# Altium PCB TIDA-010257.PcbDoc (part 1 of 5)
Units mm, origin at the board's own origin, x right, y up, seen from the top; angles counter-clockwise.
Board outline 250 x 270 mm, 2 copper layers (Top Layer, Bottom Layer), stack 1.575 mm thick; 458 components, 220 nets, 1154 pads, 1226 vias.
Unrouted connection lines stored in the file: 314.
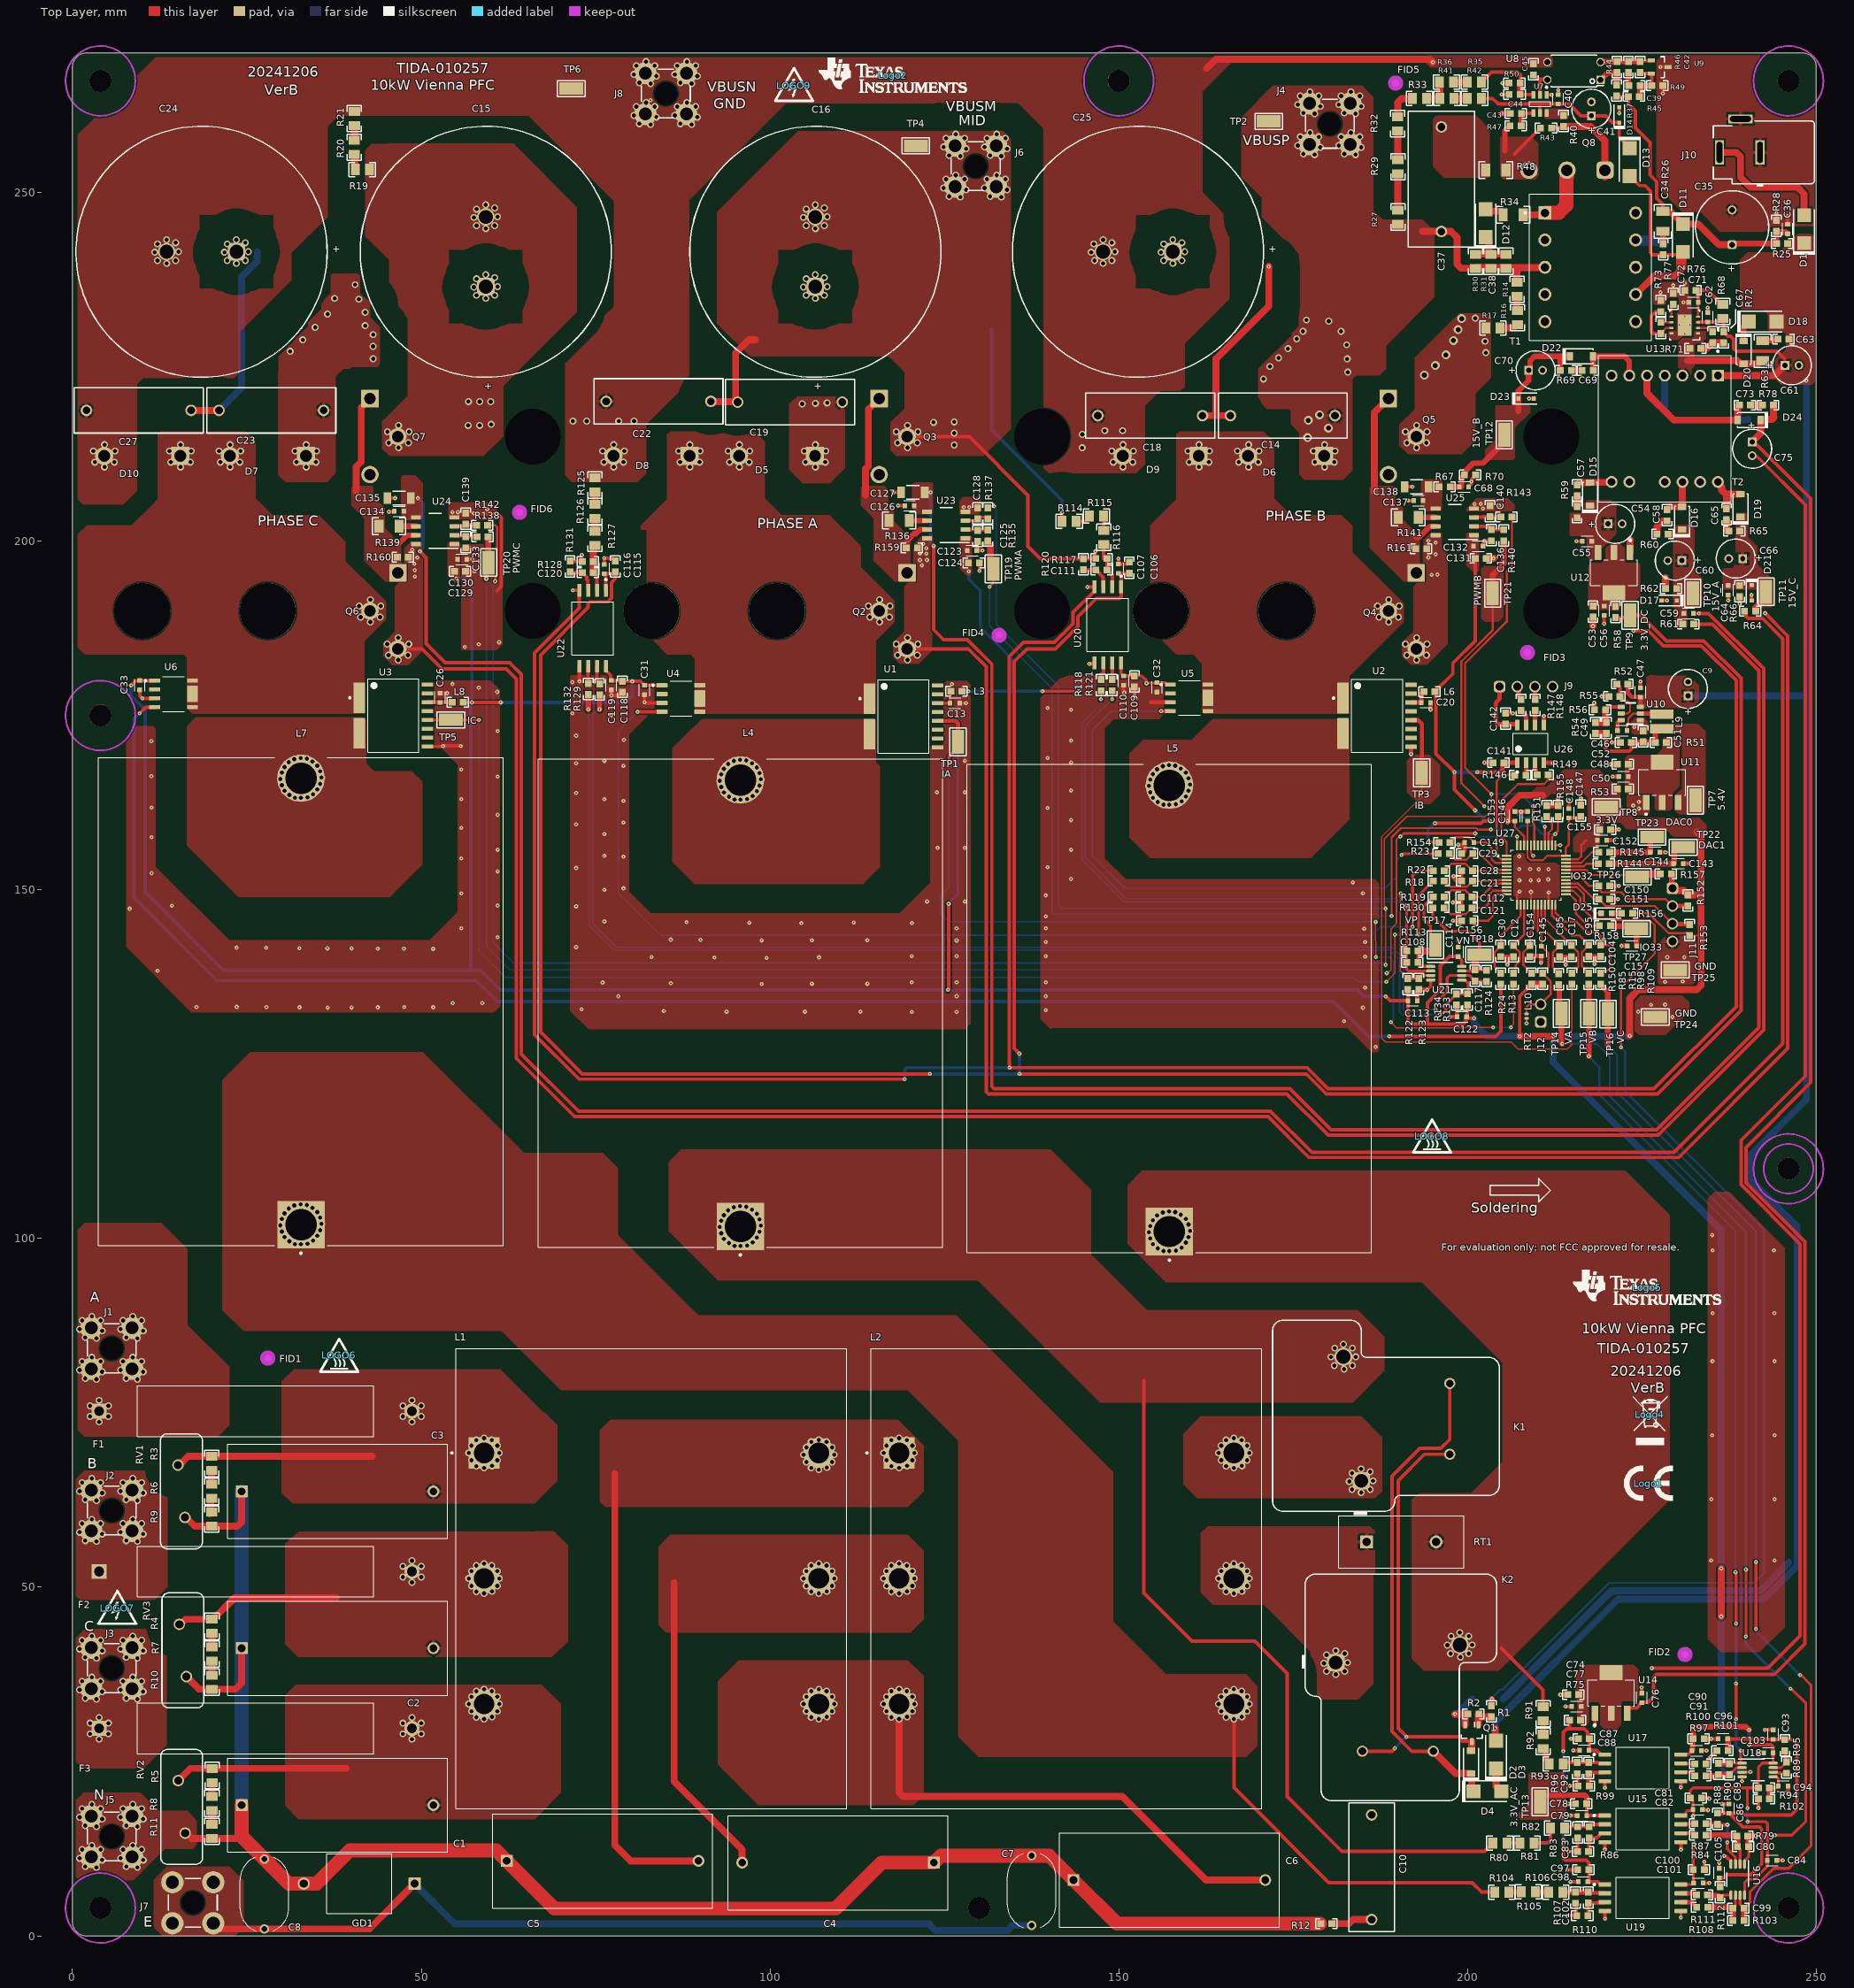
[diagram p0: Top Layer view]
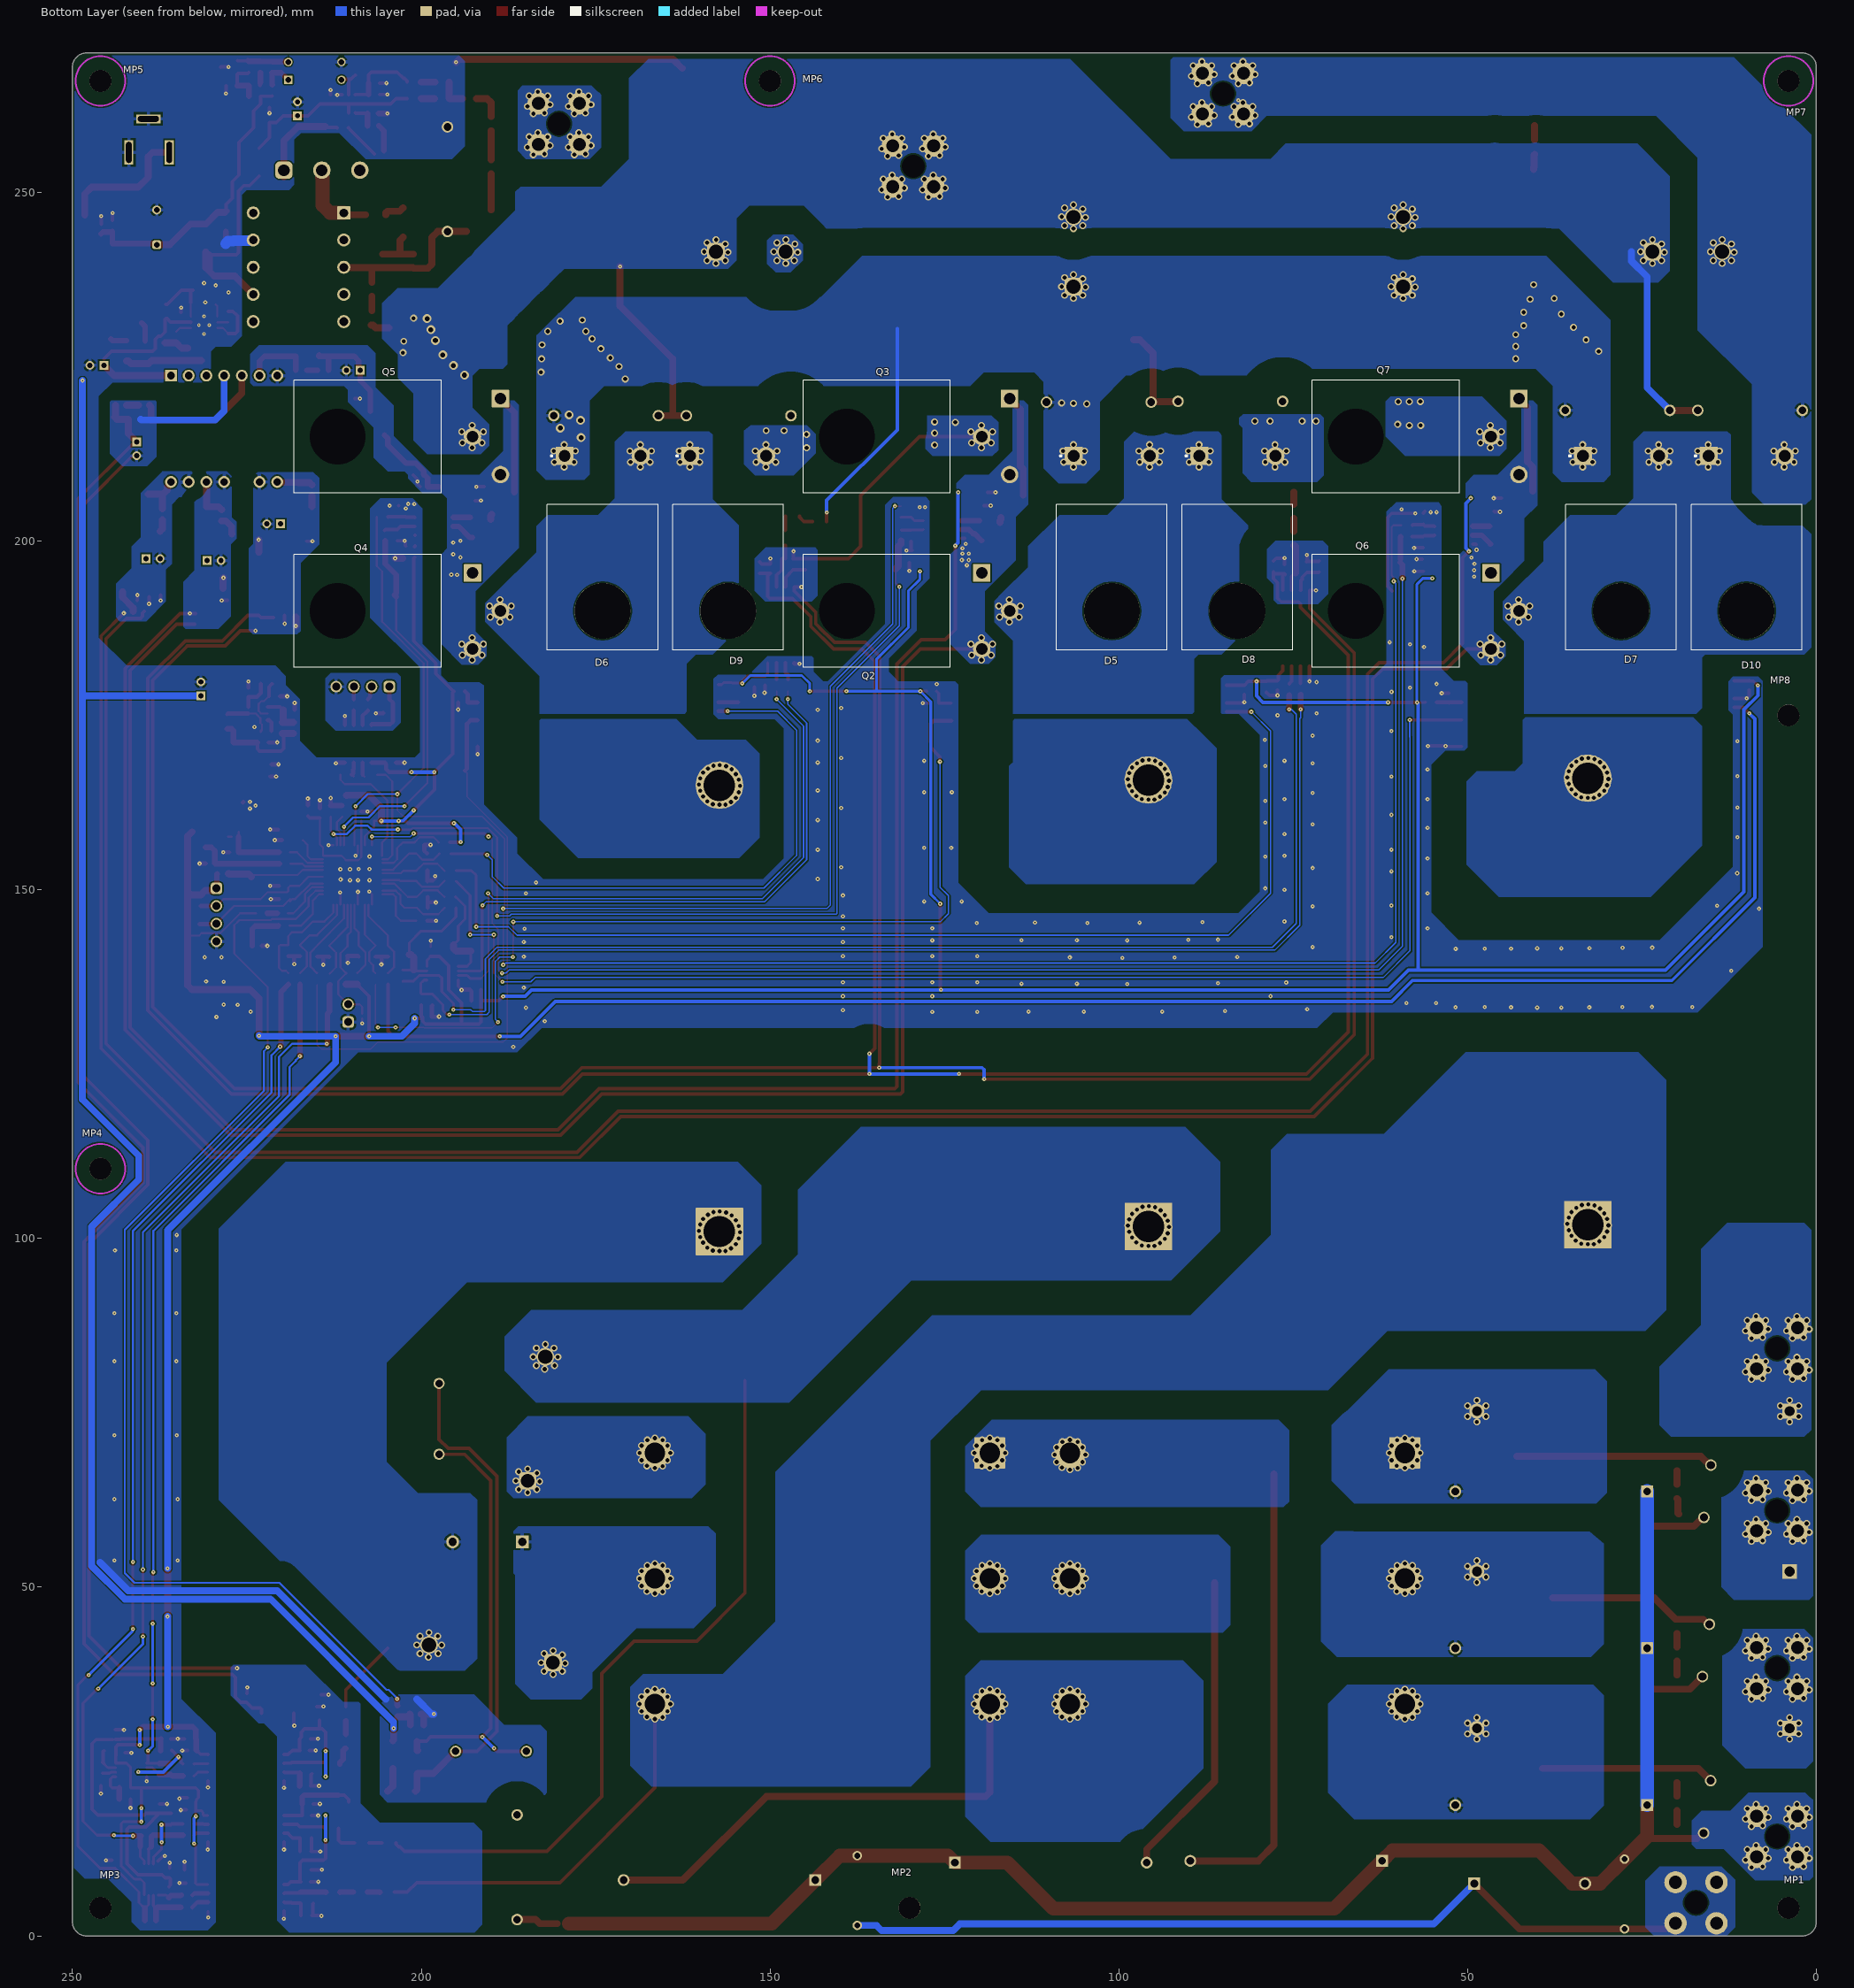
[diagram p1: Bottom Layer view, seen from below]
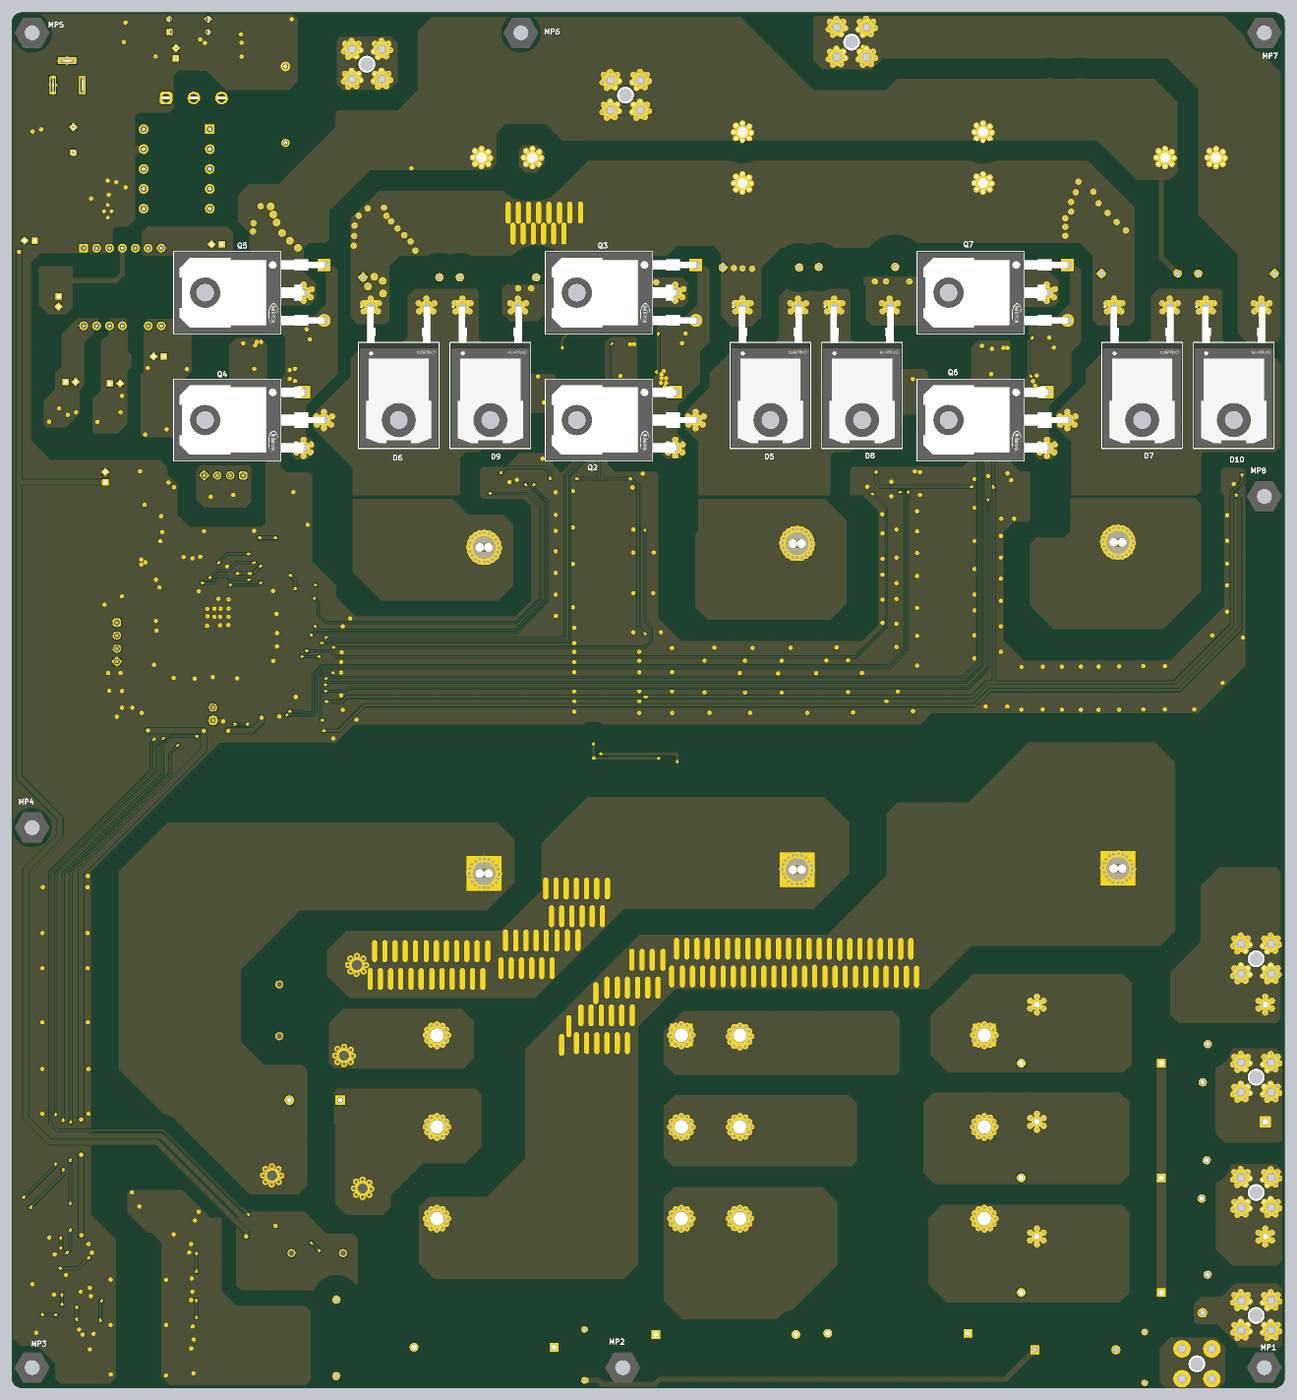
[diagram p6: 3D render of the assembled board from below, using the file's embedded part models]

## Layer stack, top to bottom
Top Solder: solder mask 0.0102, Solder Resist, Dk 3.5
Top Layer: signal copper 0.0356
Dielectric1: core 1.5037, FR-4 High Tg, Dk 4.8
Bottom Layer: signal copper 0.0356
Bottom Solder: solder mask 0.0102, Solder Resist, Dk 3.5

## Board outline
2,0 cw(c2,2) 0,2 0,268 cw(c2,268) 2,270 248,270 cw(c248,268) 250,268 250,2 cw(c248,2) 248,0

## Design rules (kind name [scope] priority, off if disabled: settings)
Clearance A2B [InNetClass('ACA') vs InNetClass('ACB')] p1: gap=4 ignorepadtopadclearanceinfootprint=FALSE
Clearance Ignore [All vs WithinRoom('Ignore1')    or WithinRoom('IsolatedPower')] p2: gap=0.2 ignorepadtopadclearanceinfootprint=FALSE
Clearance GA2B [InNetClass('GateA') vs InNetClass('ACB')] p3: gap=2 ignorepadtopadclearanceinfootprint=FALSE
Clearance GA2C [InNetClass('GateA') vs InNetClass('GateC')] p4: gap=2 ignorepadtopadclearanceinfootprint=FALSE
Clearance GB2C [InNetClass('GateB') vs InNetClass('GateC')] p5: gap=2 ignorepadtopadclearanceinfootprint=FALSE
Clearance A2C [InNetClass('ACA') vs InNetClass('ACC')] p6: gap=4 ignorepadtopadclearanceinfootprint=FALSE
Clearance B2C [InNetClass('ACB') vs InNetClass('ACC')] p7: gap=4 ignorepadtopadclearanceinfootprint=FALSE
Clearance DCBUSP2N [InNetClass('DCBUSP') vs InNetClass('PGND')] p8: gap=5.5 ignorepadtopadclearanceinfootprint=FALSE
Clearance DCBUSP2M [InNetClass('DCBUSP') vs InNetClass('DCBUSM')] p9: gap=4 ignorepadtopadclearanceinfootprint=FALSE
Clearance DCBUSM2N [InNetClass('DCBUSM') vs InNetClass('PGND')] p10: gap=2 ignorepadtopadclearanceinfootprint=FALSE
Clearance A2GND [InNetClass('ACA') vs InNetClass('PGND')] p11: gap=3 ignorepadtopadclearanceinfootprint=FALSE
Clearance B2GND [InNetClass('ACB') vs InNetClass('PGND')] p12: gap=3 ignorepadtopadclearanceinfootprint=FALSE
Clearance C2GND [InNetClass('ACC') vs InNetClass('PGND')] p13: gap=3 ignorepadtopadclearanceinfootprint=FALSE
Clearance GA2GND [InNetClass('GateA') vs InNetClass('PGND')] p14: gap=2 ignorepadtopadclearanceinfootprint=TRUE
Clearance GB2GND [InNetClass('ACB') vs InNetClass('PGND')] p15: gap=2 ignorepadtopadclearanceinfootprint=FALSE
Clearance GC2GND [InNetClass('ACC') vs InNetClass('PGND')] p16: gap=2 ignorepadtopadclearanceinfootprint=FALSE
Clearance [All] p17: gap=0.2 ignorepadtopadclearanceinfootprint=FALSE
Height [All] p1: minheight=0 maxheight=50 prefheight=12.7
HoleSize [All] p1: absolutevalues=TRUE maxlimit=10 minlimit=0.025 maxpercent=80.000 minpercent=20.000
HoleToHoleClearance [All] p1: gap=0.1 allowstackedmicrovias=TRUE
MinimumSolderMaskSliver [All] p1: minsoldermaskwidth=0.001
PolygonConnect PolygonReleif [All vs InComponent('J10') or InComponent('J35')   or  InComponent('C75') or InComponent('C54')   or InComponent('C66') or InComponent('C60') or InComponent('C35') or InComponent('C1')  or InComponent('C2') or InComponent('C3') or InComponent('C9') or InComponent('C61') or InComponent('C27') or InComponent('C23')  or InComponent('C19') or InComponent('C22')   or InComponent('C18') or InComponent('C14') or InComponent('C41') or InComponent('U8') or InComponent('C70')   or InComponent('RT1')  or InComponent('J9')  or InComponent('J11')   or InComponent('J12') or InComponent('T2')] p1: connectstyle=Relief reliefconductorwidth=0.5 reliefentries=4 polygonreliefangle="90 Angle" airgapwidth=0.3
PolygonConnect PolygonDirect [All] p2: connectstyle=Direct reliefconductorwidth=0.22 reliefentries=4 polygonreliefangle="90 Angle" airgapwidth=0.3
RoomDefinition IsolatedPower [InComponentClass('IsolatedPower')] p1: confinementstyle=ConfineIn formatcopy=TRUE lockcomponents=FALSE outline 194.153,238.75 250,238.75 250,184.359 194.153,184.359
RoomDefinition Ignore1 [InComponentClass('Components Class1')] p2: confinementstyle=ConfineIn formatcopy=TRUE lockcomponents=FALSE outline 161.5,268.27 162.879,270 221.417,270 223.25,267.699 223.25,240.373 220.006,236.301 170.181,236.301 161.5,247.198
RoutingVias [All] p1: holewidth=0.2 width=0.6 viastyle="Through Hole" minholewidth=0.2 minwidth=0.6 maxholewidth=2.6 maxwidth=3
SilkToBoardRegionClearance [Not ((IsComment or IsDesignator) And (Hide <> 'False')) and not InRegion(1000,500,4000,800)] p1:
SilkToSilkClearance [All] p1: silktosilkclearance=0
SilkToSolderMaskClearance [IsPad] p1: minsilkscreentomaskgap=0 clearancetoexposedcopper=TRUE
SolderMaskExpansion [All] p1: expansion=0.102 istentingtop=FALSE
Width [All] p1: maxlimit=5 minlimit=0.2 preferedwidth=0.2 minimp=50.000000 maximp=50.000000 favimp=50.000000
23 further rules are at their usual default settings.

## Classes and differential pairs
net class PGND: 1.65V 3.3V 5.4V 5V_ISO 15V #GD_ENABLE A3.3V BROWNOUT DAC0 DAC1 GND_ISO HS_TEMP_AD IA_AD IB_AD IC_AD LED1C_C2K MCU_TCK MCU_TMS NetC34_1 NetC35_1 NetC39_1 NetC39_2 NetC40_2 NetC42_2 NetC43_1 NetC45_2 NetC46_1 NetC46_2 NetC48_1 NetC49_1 NetC63_2 NetC67_1 NetC71_2 NetC72_1 NetC80_1 NetC80_2 NetC89_1 NetC89_2 NetC94_2 NetC99_1 NetC99_2 NetC108_1 NetC108_2 NetC117_1 NetC117_2 NetC125_1 NetC128_1 NetC133_1 NetC136_1 NetC139_1 NetC140_1 NetC143_2 NetC144_2 NetC146_1 NetC156_1 NetC157_2 NetD3_1 NetD18_1 NetD20_2 NetD25_1 NetQ1_1 NetQ8_1 NetQ8_3 NetR22_2 NetR23_2 NetR24_2 NetR33_1 NetR35_2 NetR37_1 NetR40_1 NetR41_2 NetR52_1 NetR72_1 NetR73_1 NetR73_2 NetR84_1 NetR87_1 NetR87_2 NetR89_1 NetR89_2 NetR97_1 NetR100_1 NetR100_2 NetR108_1 NetR111_1 NetR111_2 NetR118_1 NetR121_1 NetR121_2 NetR129_1 NetR132_1 NetR132_2 NetR146_2 NetR147_1 NetR148_1 NetR149_2 NetR151_1 NetR157_1 NetR158_1 NetU4_2 NetU5_2 NetU6_2 NetU24_4 NetU24_7 NetU24_10 NetU24_16 NetU24_27 NetU24_29 NetU24_31 NetU24_39 NetU24_41 NetU24_47 PWMA PWMB PWMC RELAY RELAY_DRIVE RX SYS_RX SYS_TX TMPA TMPB TMPC TX V_BUSN_AD V_BUSP_AD V_Relay VA_AD Vaux VB_AD VBUSN VC_AD XRSn
net class GateC: 15V_GateC GND_GATEC NetC64_2 NetC65_1 NetC65_2 NetR139_1 QC_C QC_GATE
net class GateB: 15V_GateB GND_GATEB NetC68_2 NetC69_1 NetC69_2 NetR141_1 QB_C QB_GATE
net class GateA: 15V_GateA GND_GATEA NetC58_1 NetC58_2 NetC59_2 NetR136_1 QA_C QA_GATE
net class EARTH: EGND NetC1_2 V_L3
net class DCBUSP: NetC38_2 NetD12_2 NetQ8_2 NetR27_1 NetR29_1 NetR32_1 NetR33_1 NetT1_2 VBUSP
net class DCBUSM: 3.3V_DCSensing NetC53_1 NetC54_1 NetC57_1 NetC57_2 NetC111_1 NetC111_2 NetC120_1 NetC120_2 NetR115_2 NetR126_2 NetU11_4 VBUSM VBUSP
net class ACB: NetC2_2 NetC4_2 NetK2_1 QB_C V_B V_B2 V_L2 VBUSM VN
net class ACN: 3.3V_ACSensing GND_ACSensing NetC10_1 NetC73_1 NetC73_2 NetC74_1 NetC75_1 NetC83_1 NetC83_2 NetC92_1 NetC92_2 NetC102_1 NetC102_2 NetR81_2 NetR92_2 NetR105_2 NetU9_4 VN
net class ACC: EGND NetC1_2 NetC6_2 NetL7_2 QC_C V_C V_L3 VN
net class ACA: NetC3_2 NetC5_2 NetK1_1 NetL4_2 QA_C V_A V_L1 VN
component class PowerStage: C12 C13 C14 C15 C16 C17 C18 C19 C20 C21 C22 C23 C24 C25 C26 C27 C28 C29 C30 C31 C32 C33 D5 D6 D7 D8 D9 D10 L3 L4 L5 L6 L7 L8 Q2 Q3 Q4 Q5 Q6 Q7 R13 R14 R15 R16 R17 R18 R19 R20 R21 R22 R23 R24 TP1 TP2 TP3 TP4 TP5 TP6 U1 U2 U3 U4 U5 U6
component class OutputVoltageSensing: C106 C107 C108 C109 C110 C111 C112 C113 C114 C115 C116 C117 C118 C119 C120 C121 C122 R113 R114 R115 R116 R117 R118 R119 R120 R121 R122 R123 R124 R125 R126 R127 R128 R129 R130 R131 R132 R133 R134 TP17 TP18 U20 U21 U22
component class Main: D1 J1 J2 J3 J4 J5 J6 J7 J8 J9 J10
component class IsolatedPower: C53 C54 C55 C56 C57 C58 C59 C60 C61 C62 C63 C64 C65 C66 C67 C68 C69 C70 C71 C72 C73 C74 C75 C76 C77 D15 D16 D17 D18 D19 D20 D21 D22 D23 D24 R58 R59 R60 R61 R62 R63 R64 R65 R66 R67 R68 R69 R70 R71 R72 R73 R75 R76 R77 R78 T2 TP9 TP10 TP11 TP12 TP13 U12 U13 U14
component class InputVoltageSensing: C78 C79 C80 C81 C82 C83 C84 C85 C86 C87 C88 C89 C90 C91 C92 C93 C94 C95 C96 C97 C98 C99 C100 C101 C102 C103 C104 C105 R79 R80 R81 R82 R83 R84 R85 R86 R87 R88 R89 R90 R91 R92 R93 R94 R95 R96 R97 R98 R99 R100 R101 R102 R103 R104 R105 R106 R107 R108 R109 R110 R111 R112 TP14 TP15 TP16 U15 U16 U17 U18 U19
component class Header: J9 J11 J12
component class GateDrivers: C123 C124 C125 C126 C127 C128 C129 C130 C131 C132 C133 C134 C135 C136 C137 C138 C139 C140 R135 R136 R137 R138 R139 R140 R141 R142 R143 R159 R160 R161 TP19 TP20 TP21 U23 U24 U25
component class EMCInputFilter: C1 C2 C3 C4 C5 C6 C7 C8 C10 D2 D3 D4 F1 F2 F3 GD1 K1 K2 L1 L2 Q1 R1 R2 R3 R4 R5 R6 R7 R8 R9 R10 R11 R12 RT1 RV1 RV2 RV3
component class Controller: C141 C142 C143 C144 C145 C146 C147 C148 C149 C150 C151 C152 C153 C154 C155 C156 C157 D25 J11 J12 L10 R144 R145 R146 R147 R148 R149 R150 R151 R152 R153 R154 R155 R156 R157 R158 RT2 TP22 TP23 TP24 TP25 TP26 TP27 U26 U27
component class AuxPower: C9 C34 C35 C36 C37 C38 C39 C40 C41 C42 C43 C44 C45 C46 C47 C48 C49 C50 C51 C52 D11 D12 D13 D14 L9 Q8 R25 R26 R27 R28 R29 R30 R31 R32 R33 R34 R35 R36 R37 R40 R41 R42 R43 R44 R45 R46 R47 R48 R49 R50 R51 R52 R53 R54 R55 R56 T1 TP7 TP8 U7 U8 U9 U10 U11
component class Logo: Logo2 Logo5
component class Hardware: FID1 FID2 FID3 FID4 FID5 FID6 Logo1 Logo2 Logo3 Logo4 Logo5 LOGO6 LOGO7 LOGO8 LOGO9 MP1 MP2 MP3 MP4 MP5 MP6 MP7 MP8
component class FiducialMark: FID1 FID2 FID3 FID4 FID5 FID6

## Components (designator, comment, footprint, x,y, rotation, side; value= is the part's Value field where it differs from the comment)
C1 "890334027012CS" FP-890334027012CS_RADIAL-MFG 38,18.75 r0 top value=1.2µF
C2 "890334027012CS" FP-890334027012CS_RADIAL-MFG 38,41.25 r0 top value=1.2µF
C3 "890334027012CS" FP-890334027012CS_RADIAL-MFG 38,63.75 r0 top value=1.2µF
C4 "890334027012CS" FP-890334027012CS_RADIAL-MFG 109.75,10.5 r180 top value=1.2µF
C5 "890334027012CS" FP-890334027012CS_RADIAL-MFG 76,10.75 r0 top value=1.2µF
C6 "890334027012CS" FP-890334027012CS_RADIAL-MFG 157.25,8 r0 top value=1.2µF
C7 "DE1E3KX222MA4BL01" CAPRD1000W60D900H1200 137.5,6.5 r270 top value=2200pF
C8 "DE1E3KX222MA4BL01" CAPRD1000W60D900H1200 27.5,6 r270 top value=2200pF
C9 "EKZN350ELL470ME11D" Chemi-Con_500x1100 231.591,178.82 r90 top value=47uF
C10 "890334025017" WCAP-FTXX_P15PL20_1800x600 186.25,9.846 r90 top value=0.1uF
C12 "GRM188R71H102KA01D" 0603 206.563,141.215 r270 top value=1000pF
C13 "GCM188R71H104KA57J" FP-GCM188R71H104KA57J_0603-MFG 126.5,176.78 r0 top value=100nF
C14 "890334025017" WCAP-FTXX_P15PL20_1800x600 173.5,218 r180 top value=0.1uF
C15 "MAL215757471E3" 157PUM-SI_3500x5000 59.25,241.5 r90 top locked value=470uF
C16 "MAL215757471E3" 157PUM-SI_3500x5000 106.5,241.5 r90 top locked value=470uF
C17 "GRM188R71H102KA01D" 0603 214.904,141.228 r270 top value=1000pF
C18 "890334025017" WCAP-FTXX_P15PL20_1800x600 154.5,218 r180 top value=0.1uF
C19 "890334025017" WCAP-FTXX_P15PL20_1800x600 102.86,219.935 r180 top value=0.1uF
C20 "GCM188R71H104KA57J" FP-GCM188R71H104KA57J_0603-MFG 194.028,176.862 r0 top value=100nF
C21 "GRM188R71H102KA01D" 0603 199.914,151.252 r180 top value=1000pF
C22 "890334025017" WCAP-FTXX_P15PL20_1800x600 84.009,220.053 r180 top value=0.1uF
C23 "890334025017" WCAP-FTXX_P15PL20_1800x600 28.5,218.75 r180 top value=0.1uF
C24 "MAL215757471E3" 157PUM-SI_3500x5000 18.5,241.5 r180 top locked value=470uF
C25 "MAL215757471E3" 157PUM-SI_3500x5000 152.75,241.5 r180 top locked value=470uF
C26 "GCM188R71H104KA57J" FP-GCM188R71H104KA57J_0603-MFG 52.683,177.54 r90 top value=100nF
C27 "890334025017" WCAP-FTXX_P15PL20_1800x600 9.5,218.75 r180 top value=0.1uF
C28 "GRM188R71H102KA01D" 0603 199.914,152.752 r180 top value=1000pF
C29 "GRM188R71H102KA01D" 0603 199.949,155.22 r180 top value=1000pF
C30 "GRM188R71H102KA01D" 0603 204.772,141.218 r270 top value=1000pF
C31 "GCM188R71H104KA57J" FP-GCM188R71H104KA57J_0603-MFG 82,178.659 r90 top value=100nF
C32 "GCM188R71H104KA57J" FP-GCM188R71H104KA57J_0603-MFG 155.486,179.03 r90 top value=100nF
C33 "GCM188R71H104KA57J" FP-GCM188R71H104KA57J_0603-MFG 9.646,179.343 r90 top value=100nF
C34 "GRM1885C2A101JA01D" 0603 228.058,241.868 r270 top value=100pF
C35 "35ZLG470MEFC10X20" ZLG_1000x2000 237.924,245 r90 top value=470uF
C36 "GCM188R71H104KA57J" FP-GCM188R71H104KA57J_0603-MFG 245.885,244.75 r270 top value=100nF
C37 "890493425009CS" WCAP-FTBE_L18W8.5H15 196.25,251.907 r270 top
C38 "GRM21AR72E102KW01D" 0805_HV 205.521,240.141 r90 top value=1000pF
C39 "GRM188R71H102KA01D" 0603 223.935,265.328 r0 top value=1000pF
C40 "GCM188R71H104KA57J" FP-GCM188R71H104KA57J_0603-MFG 213,263.375 r270 top value=100nF
C41 "UPW1V100MDD6" PW_500x700 217.75,262 r90 top value=10uF
C42 "GRM1885C2A101JA01D" 0603 224.75,268.007 r90 top value=100pF
C43 "885012206081" 0603 206.921,261.344 r180 top value=470pF
C44 "GRM1885C2A101JA01D" 0603 206.746,264.062 r180 top value=100pF
C45 "GRM188R71H102KA01D" 0603 209.46,267.653 r270 top value=1000pF
C46 "GCM188R71H104KA57J" FP-GCM188R71H104KA57J_0603-MFG 222.168,172.822 r180 top value=100nF
C47 "GCM188R71H104KA57J" FP-GCM188R71H104KA57J_0603-MFG 224.776,178.309 r270 top value=100nF
C48 "GRM188Z71A106MA73D" 0603 222.253,168 r180 top value=10uF
C49 "GRM1885C2A101JA01D" 0603 219.903,173.226 r270 top value=100pF
C50 "GCM188R71H104KA57J" FP-GCM188R71H104KA57J_0603-MFG 222.355,166.25 r0 top value=100nF
C51 "GRM188Z71A106MA73D" 0603 225.151,172.016 r90 top value=10uF
C52 "GRM188Z71A106MA73D" 0603 222.701,171.129 r180 top value=10uF
C53 "GRM188Z71A106MA73D" 0603 217.975,189.91 r270 top value=10uF
C54 "EKZN350ELL470ME11D" Chemi-Con_500x1100 221.156,202.487 r0 top value=47uF
C55 "GCM188R71H104KA57J" FP-GCM188R71H104KA57J_0603-MFG 217.143,199.993 r0 top value=100nF
C56 "GCM188R71H104KA57J" FP-GCM188R71H104KA57J_0603-MFG 219.578,190.035 r90 top value=100nF
C57 "GRM1885C2A101JA01D" 0603 215.691,207.275 r90 top value=100pF
C58 "GRM1885C2A101JA01D" 0603 228.611,203.707 r90 top value=100pF
C59 "GCM188R71H104KA57J" FP-GCM188R71H104KA57J_0603-MFG 231.691,189.637 r180 top value=100nF
C60 "EKZN350ELL470ME11D" Chemi-Con_500x1100 229.711,197.211 r180 top value=47uF
C61 "EKZN350ELL470ME11D" Chemi-Con_500x1100 246.5,225.22 r0 top value=47uF
C62 "GCM188R71H104KA57J" FP-GCM188R71H104KA57J_0603-MFG 234.453,232.117 r270 top value=100nF
C63 "GRM1885C2A101JA01D" 0603 245.294,228.983 r180 top value=100pF
C64 "GCM188R71H104KA57J" FP-GCM188R71H104KA57J_0603-MFG 237.371,192.975 r90 top value=100nF
C65 "GRM1885C2A101JA01D" 0603 237.127,203.865 r90 top value=100pF
C66 "EKZN350ELL470ME11D" Chemi-Con_500x1100 238.448,197.5 r180 top value=47uF
C67 "GRM1885C2A101JA01D" 0603 236.71,229.221 r90 top value=100pF
C68 "GCM188R71H104KA57J" FP-GCM188R71H104KA57J_0603-MFG 199.489,207.807 r180 top value=100nF
C69 "GRM1885C2A101JA01D" 0603 217.215,224.5 r0 top value=100pF
C70 "EKZN350ELL470ME11D" Chemi-Con_500x1100 209.75,224.5 r0 top value=47uF
C71 "GCM188R71H104KA57J" FP-GCM188R71H104KA57J_0603-MFG 232.376,234.238 r0 top value=100nF
C72 "GCM188R72A103KA37J" 0603 229.477,234.749 r90 top value=0.01uF
C73 "GRM1885C2A101JA01D" 0603 239.757,219.5 r180 top value=100pF
C74 "GRM188Z71A106MA73D" 0603 215.148,34.584 r180 top value=10uF
C75 "EKZN350ELL470ME11D" Chemi-Con_500x1100 240.8,213.25 r270 top value=47uF
C76 "GCM188R71H104KA57J" FP-GCM188R71H104KA57J_0603-MFG 225,34.123 r270 top value=100nF
C77 "GCM188R71H104KA57J" FP-GCM188R71H104KA57J_0603-MFG 215.622,32.892 r0 top value=100nF
C78 "GRJ188R71E105KE11D" 0603 216.275,18.923 r180 top value=1uF
C79 "GCM188R71H104KA57J" FP-GCM188R71H104KA57J_0603-MFG 216.4,17.251 r0 top value=100nF
C80 "GRM188R71H102KA01D" 0603 239.487,12.787 r180 top value=1000pF
C81 "GRJ188R71E105KE11D" 0603 232.745,19.787 r180 top value=1uF
C82 "GCM188R71H104KA57J" FP-GCM188R71H104KA57J_0603-MFG 233,18.096 r0 top value=100nF
C83 "GRM1885C2A101JA01D" 0603 217.426,14.846 r270 top value=100pF
C84 "GCM188R71H104KA57J" FP-GCM188R71H104KA57J_0603-MFG 243.649,10.832 r180 top value=100nF
C85 "GRM188R71H102KA01D" 0603 213.198,141.192 r90 top value=1000pF
C86 "GCM188R71H104KA57J" FP-GCM188R71H104KA57J_0603-MFG 237.509,18.248 r270 top value=100nF
C87 "GRJ188R71E105KE11D" 0603 216.672,28.265 r180 top value=1uF
C88 "GCM188R71H104KA57J" FP-GCM188R71H104KA57J_0603-MFG 216.736,26.603 r0 top value=100nF
C89 "GRM188R71H102KA01D" 0603 237.543,23.896 r270 top value=1000pF
C90 "GRJ188R71E105KE11D" 0603 233.125,28.265 r180 top value=1uF
C91 "GCM188R71H104KA57J" FP-GCM188R71H104KA57J_0603-MFG 232.843,26.566 r0 top value=100nF
C92 "GRM1885C2A101JA01D" 0603 217.349,24.062 r270 top value=100pF
C93 "GCM188R71H104KA57J" FP-GCM188R71H104KA57J_0603-MFG 243.816,28.868 r270 top value=100nF
C94 "GCM188R71H104KA57J" FP-GCM188R71H104KA57J_0603-MFG 245.25,21.5 r180 top value=100nF
C95 "GRM188R71H102KA01D" 0603 217.391,141.278 r90 top value=1000pF
C96 "GCM188R71H104KA57J" FP-GCM188R71H104KA57J_0603-MFG 236.617,28.265 r0 top value=100nF
C97 "GRJ188R71E105KE11D" 0603 216.587,9.469 r180 top value=1uF
C98 "GCM188R71H104KA57J" FP-GCM188R71H104KA57J_0603-MFG 216.565,7.754 r0 top value=100nF
C99 "GRM188R71H102KA01D" 0603 238.835,3.958 r180 top value=1000pF
C100 "GRJ188R71E105KE11D" 0603 233.141,9.469 r180 top value=1uF
C101 "GCM188R71H104KA57J" FP-GCM188R71H104KA57J_0603-MFG 233.076,7.567 r0 top value=100nF
C102 "GRM1885C2A101JA01D" 0603 217.315,5.498 r270 top value=100pF
C103 "GCM188R71H104KA57J" FP-GCM188R71H104KA57J_0603-MFG 243.121,26.25 r0 top value=100nF
C104 "GRM188R71H102KA01D" 0603 219.069,141.278 r90 top value=1000pF
C105 "GCM188R71H104KA57J" FP-GCM188R71H104KA57J_0603-MFG 236.076,9.009 r270 top value=100nF
C106 "GRJ188R71E105KE11D" 0603 151.5,196.214 r90 top value=1uF
C107 "GCM188R71H104KA57J" FP-GCM188R71H104KA57J_0603-MFG 149.953,196.043 r270 top value=100nF
C108 "GRM188R71H102KA01D" 0603 192.078,139.586 r180 top value=1000pF
C109 "GRJ188R71E105KE11D" 0603 152.25,179.88 r90 top value=1uF
C110 "GCM188R71H104KA57J" FP-GCM188R71H104KA57J_0603-MFG 150.69,179.995 r270 top value=100nF
C111 "GRM1885C2A101JA01D" 0603 147.5,195.868 r180 top value=100pF
C112 "GRM188R71H102KA01D" 0603 199.877,148.995 r0 top value=1000pF
C113 "GCM188R71H104KA57J" FP-GCM188R71H104KA57J_0603-MFG 192.125,134.101 r180 top value=100nF
C114 "GCM188R71H104KA57J" FP-GCM188R71H104KA57J_0603-MFG 198.648,141.106 r90 top value=100nF
C115 "GRJ188R71E105KE11D" 0603 77.815,196.366 r90 top value=1uF
C116 "GCM188R71H104KA57J" FP-GCM188R71H104KA57J_0603-MFG 76.25,196 r270 top value=100nF
C117 "GRM188R71H102KA01D" 0603 201.092,137.719 r270 top value=1000pF
C118 "GRJ188R71E105KE11D" 0603 78.815,179.105 r90 top value=1uF
C119 "GCM188R71H104KA57J" FP-GCM188R71H104KA57J_0603-MFG 77.25,179.346 r270 top value=100nF
C120 "GRM1885C2A101JA01D" 0603 73.874,195.475 r180 top value=100pF
C121 "GRM188R71H102KA01D" 0603 199.877,147.428 r0 top value=1000pF
C122 "GCM188R71H104KA57J" FP-GCM188R71H104KA57J_0603-MFG 199.18,131.8 r0 top value=100nF
C123 "GRJ188R71E105KE11D" 0603 129.227,196.905 r0 top value=1uF
C124 "GCM188R71H104KA57J" FP-GCM188R71H104KA57J_0603-MFG 128.963,198.668 r180 top value=100nF
C125 "GRM188R71H102KA01D" 0603 129.75,200.75 r270 top value=1000pF
C126 "GCM188R71H104KA57J" FP-GCM188R71H104KA57J_0603-MFG 120.004,205.093 r0 top value=100nF
C127 "GRM31CR61H106KA12L" 1206_180 120.484,207 r180 top value=10uF
C128 "GRM188R71H102KA01D" 0603 129.75,203.971 r90 top value=1000pF
C129 "GRJ188R71E105KE11D" 0603 55.55,195.675 r0 top value=1uF
C130 "GCM188R71H104KA57J" FP-GCM188R71H104KA57J_0603-MFG 55.85,197.402 r180 top value=100nF
C131 "GRJ188R71E105KE11D" 0603 201.876,197.542 r0 top value=1uF
C132 "GCM188R71H104KA57J" FP-GCM188R71H104KA57J_0603-MFG 201.539,199.292 r180 top value=100nF
C133 "GRM188R71H102KA01D" 0603 56.374,199.843 r270 top value=1000pF
C134 "GCM188R71H104KA57J" FP-GCM188R71H104KA57J_0603-MFG 46.825,204.274 r0 top value=100nF
C135 "GRM31CR61H106KA12L" 1206_180 46.825,206.169 r180 top value=10uF
C136 "GRM188R71H102KA01D" 0603 203.436,200.857 r270 top value=1000pF
C137 "GCM188R71H104KA57J" FP-GCM188R71H104KA57J_0603-MFG 192.954,205.816 r0 top value=100nF
C138 "GRM31CR61H106KA12L" 1206_180 192.687,207.807 r180 top value=10uF
C139 "GRM188R71H102KA01D" 0603 56.35,203.24 r90 top value=1000pF
C140 "GRM188R71H102KA01D" 0603 203.209,204.303 r90 top value=1000pF
C141 "GRJ188R71E105KE11D" 0603 204.437,168.237 r0 top value=1uF
C142 "GRJ188R71E105KE11D" 0603 205.458,174.559 r90 top value=1uF
C143 "GCM188R71H104KA57J" FP-GCM188R71H104KA57J_0603-MFG 230.226,153.766 r180 top value=100nF
C144 "GCM188R71H104KA57J" FP-GCM188R71H104KA57J_0603-MFG 226.865,155.402 r180 top value=100nF
C145 "GCM188R71H104KA57J" FP-GCM188R71H104KA57J_0603-MFG 210.588,141.218 r90 top value=100nF
C146 "GCM188R71H104KA57J" FP-GCM188R71H104KA57J_0603-MFG 208.588,160.552 r90 top value=100nF
C147 "GRM188Z71A106MA73D" 0603 216.248,161.338 r270 top value=10uF
C148 "GCM188R71H104KA57J" FP-GCM188R71H104KA57J_0603-MFG 214.532,160.988 r90 top value=100nF
C149 "GCM188R71H104KA57J" FP-GCM188R71H104KA57J_0603-MFG 200.242,156.812 r0 top value=100nF
C150 "GRM1885C2A101JA01D" 0603 219.605,150.559 r0 top value=100pF
C151 "GRM1885C2A101JA01D" 0603 219.592,148.684 r0 top value=100pF
C152 "GCM188R71H104KA57J" FP-GCM188R71H104KA57J_0603-MFG 219.263,157.127 r180 top value=100nF
C153 "GCM188R71H104KA57J" FP-GCM188R71H104KA57J_0603-MFG 206.78,160.552 r270 top value=100nF
C154 "GRM188Z71A106MA73D" 0603 208.963,141.218 r270 top value=10uF
C155 "GRM188Z71A106MA73D" 0603 219.734,158.638 r180 top value=10uF
C156 "GRM188R71A225KE15J" 0603 199.953,145.578 r180 top value=2.2uF
C157 "GCM188R71H104KA57J" FP-GCM188R71H104KA57J_0603-MFG 223.561,141.967 r0 top value=100nF
D1 "S1MTR" SMA 248.25,244.75 r90 top value=1000V
D2 "BAT54T1G" SOD-123 200.499,24.932 r90 top value=30V
D3 "S1MTR" SMA 204.086,26 r90 top value=1000V
D4 "S1MTR" SMA 202.831,20.729 r0 top value=1000V
D5 "RHRG30120" FP-RHRG30120-MFG_HOR 101,194.825 r0 bottom locked
D6 "RHRG30120" FP-RHRG30120-MFG_HOR 174,194.825 r0 bottom locked
D7 "RHRG30120" FP-RHRG30120-MFG_HOR 28,194.825 r0 bottom
D8 "RHRG30120" FP-RHRG30120-MFG_HOR 83,194.825 r0 bottom locked
D9 "RHRG30120" FP-RHRG30120-MFG_HOR 156,194.825 r0 bottom locked
D10 "RHRG30120" FP-RHRG30120-MFG_HOR 10,194.825 r0 bottom
D11 "B2100A-13-F" SMA 230.872,243.48 r270 top value=100V
D12 "S1MTR" SMA 202.589,245.597 r90 top value=1000V
D13 "B2100A-13-F" SMA 223.25,254.36 r270 top value=100V
D14 "MMSZ5248BS-7-F" SOD-323 221.75,261.107 r90 top value=18V
D15 "MBR1H100SFT3G" SOD-123FL 217.557,206.742 r90 top value=100V
D16 "MBR1H100SFT3G" SOD-123FL 230.768,203.295 r90 top value=100V
D17 "MMSZ5248BS-7-F" SOD-323 228.901,191.5 r180 top value=18V
D18 "SMAJ20A" SMA 242.287,231.488 r0 top value=20V
D19 "MBR1H100SFT3G" SOD-123FL 239.135,205.104 r90 top value=100V
D20 "MBR1H100SFT3G" SOD-123FL 239.581,227.061 r270 top value=100V
D21 "MMSZ5248BS-7-F" SOD-323 240.75,192.6 r270 top value=18V
D22 "MBR1H100SFT3G" SOD-123FL 216.326,226.5 r0 top value=100V
D23 "MMSZ5248BS-7-F" SOD-323 208.397,220.45 r0 top value=18V
D24 "MBR1H100SFT3G" SOD-123FL 240.368,217.378 r180 top value=100V
D25 "LTST-C193KRKT-5A" LTST-C193_Red 219.908,146.628 r180 top value=Red
F1 "0525025.MXEP" FP-0525025.MXEP_AXIAL-MFG 26.25,75.25 r0 top
F2 "0525025.MXEP" FP-0525025.MXEP_AXIAL-MFG 26.25,52.25 r0 top
F3 "0525025.MXEP" FP-0525025.MXEP_AXIAL-MFG 26.25,29.75 r0 top
FID1 "Fiducial" Fiducial10-20 28,82.856 r90 top
FID2 "Fiducial" Fiducial10-20 231.177,40.354 r90 top
FID3 "Fiducial" Fiducial10-20 208.588,184.037 r90 top
FID4 "Fiducial" Fiducial10-20 132.838,186.498 r90 top
FID5 "Fiducial" Fiducial10-20 189.7,265.692 r90 top
FID6 "Fiducial" Fiducial10-20 64.092,204.125 r90 top
GD1 "SA2-3000-CLT-STD" FP-SA2-3000-CLT-STD_AXIAL-MFG 41.104,7.5 r180 top
J1 "74650073R" Wurth_WP-THRBU 5.624,84.25 r180 top
J2 "74650073R" Wurth_WP-THRBU 5.624,61 r180 top
J3 "74650073R" Wurth_WP-THRBU 5.624,38.385 r180 top
J4 "74650073R" Wurth_WP-THRBU 180.257,259.85 r90 top
J5 "74650073R" Wurth_WP-THRBU 5.624,14.25 r180 top
J6 "74650073R" Wurth_WP-THRBU 129.476,253.772 r270 top
J7 "74650073R" Wurth_WP-THRBU 17.25,4.75 r90 top
J8 "74650073R" Wurth_WP-THRBU 85.065,264.18 r180 top
J9 "61300411121" WURTH_61300411121 208.388,179.131 r0 top
J10 "694106301002" Wurth_694106301002 239.024,255.75 r270 top
J11 "61300411121" WURTH_61300411121 229.364,146.416 r270 top
J12 "61300211121" WURTH_61300211121 210.477,132.313 r90 top
K1 "T9AS1D12-15" Relay_T9AS1D12 189.83,74.14 r90 top locked
K2 "T9AS1D12-15" Relay_T9AS1D12 190,34.099 r0 top locked
L1 "YXS80874T" FP-YXS80874T_PTH_CMC_66MM0_56MM0-MFG 83,51.25 r0 top
L2 "YXS80874T" FP-YXS80874T_PTH_CMC_66MM0_56MM0-MFG 142.5,51.25 r0 top
L3 "742792662" 0603 126.731,178.476 r180 top value="1000 ohm"
L4 "YXS51020T" FP-YXS51020T_PTH_IND_58MM0_70MM0-MFG 95.75,133.75 r90 top value=355uH
L5 "YXS51020T" FP-YXS51020T_PTH_IND_58MM0_70MM0-MFG 157.25,133 r90 top value=355uH
L6 "742792662" 0603 194.524,178.44 r180 top value="1000 ohm"
L7 "YXS51020T" FP-YXS51020T_PTH_IND_58MM0_70MM0-MFG 32.75,134 r90 top value=355uH
L8 "742792662" 0603 55.236,176.905 r180 top value="1000 ohm"
L9 "78438335068" WE-MAIA_3015 227.829,174.148 r270 top value=6.8uH
L10 "742792662" 0603 209.163,137.24 r90 top value="1000 ohm"
Logo1 "CE Mark" CE_Mark_5mm 225.933,64.9 r0 top
Logo2 "Texas Instruments" TI_Stacked_Overlay_Small 117.6,266.8 r0 top
Logo3 "FCC disclaimer" FCC_disclaimer 335.62,77.246 r90 top
Logo4 "WEEE logo" WEEE_Minimum 226.129,74.75 r0 top
Logo5 "Texas Instruments" TI_Stacked_Overlay_Small 225.75,93 r0 top
LOGO6 "CAUTION HOT SURFACE" IEC_HotSurface_Small 38.25,83.25 r0 top
LOGO7 "DANGER HIGH VOLTAGE" IEC_HighVoltage_Small 6.425,47 r0 top
LOGO8 "CAUTION HOT SURFACE" IEC_HotSurface_Small 194.923,114.7 r0 top
LOGO9 "DANGER HIGH VOLTAGE" IEC_HighVoltage_Small 103.456,265.36 r0 top
MP1 "970130365" FP-970130365_SPCAER_M3-MFG 4,4 r180 bottom locked
MP2 "970130365" FP-970130365_SPCAER_M3-MFG 130,4 r180 bottom
MP3 "970130365" FP-970130365_SPCAER_M3-MFG 246,4 r180 bottom locked
MP4 "970130365" FP-970130365_SPCAER_M3-MFG 246,110 r180 bottom
MP5 "970130365" FP-970130365_SPCAER_M3-MFG 246,266 r180 bottom
MP6 "970130365" FP-970130365_SPCAER_M3-MFG 150,266 r180 bottom
MP7 "970130365" FP-970130365_SPCAER_M3-MFG 4,266 r180 bottom
MP8 "970130365" FP-970130365_SPCAER_M3-MFG 4,175 r180 bottom
Q1 "2V7002KT1G" SOT-23 200.612,29.06 r270 top value=60V
Q2 "IKW50N65F5FKSA1" FP-IKW50N65F5FKSA1_HOR_V1 134.695,190 r270 bottom locked value=650V
Q3 "IKW50N65F5FKSA1" FP-IKW50N65F5FKSA1_HOR_V2 134.695,215 r270 bottom locked value=650V
Q4 "IKW50N65F5FKSA1" FP-IKW50N65F5FKSA1_HOR_V1 207.695,190 r270 bottom locked value=650V
Q5 "IKW50N65F5FKSA1" FP-IKW50N65F5FKSA1_HOR_V2 207.695,215 r270 bottom locked value=650V
Q6 "IKW50N65F5FKSA1" FP-IKW50N65F5FKSA1_HOR_V1 61.695,190 r270 bottom locked value=650V
Q7 "IKW50N65F5FKSA1" FP-IKW50N65F5FKSA1_HOR_V2 61.695,215 r270 bottom locked value=650V
Q8 "2SK1835-E" TO-3P 214.25,253.204 r180 top value=1500V
R1 "RC0603FR-07100RL" 0603 203.395,32.203 r90 top value=100
R2 "RC0603FR-0710KL" 0603 200.838,31.809 r180 top value=10.0k
R3 "ERJ-6ENF1004V" 0805_HV 19.95,67.734 r90 top value=1.00Meg
R4 "ERJ-6ENF1004V" 0805_HV 19.991,44.384 r90 top value=1.00Meg
R5 "ERJ-6ENF1004V" 0805_HV 20,23 r90 top value=1.00Meg
R6 "ERJ-6ENF1004V" 0805_HV 19.95,63.734 r90 top value=1.00Meg
R7 "ERJ-6ENF1004V" 0805_HV 19.991,40.4 r90 top value=1.00Meg
R8 "ERJ-6ENF1004V" 0805_HV 19.991,19 r90 top value=1.00Meg
R9 "ERJ-6ENF1004V" 0805_HV 19.95,59.75 r90 top value=1.00Meg
R10 "ERJ-6ENF1004V" 0805_HV 19.991,36.384 r90 top value=1.00Meg
R11 "ERJ-6ENF1004V" 0805_HV 19.991,15 r90 top value=1.00Meg
R12 "RC0603JR-070RL" 0603 179.75,1.75 r180 top value=0
R13 "RC0603FR-071KL" 0603 206.578,137.24 r270 top value=1.00k
R14 "ERJ-6ENF1004V" 0805_HV 207.073,236.121 r90 top value=1.00Meg
R15 "RC0603FR-071KL" 0603 214.963,137.24 r270 top value=1.00k
R16 "ERJ-6ENF1004V" 0805_HV 207.175,232.076 r90 top value=1.00Meg
R17 "ERJ-6ENF1004V" 0805_HV 203.638,230.583 r0 top value=1.00Meg
R18 "RC0603FR-071KL" 0603 195.868,151.252 r180 top value=1.00k
R19 "ERJ-6ENF1004V" 0805_HV 41.53,253.3 r0 top value=1.00Meg
R20 "ERJ-6ENF1004V" 0805_HV 40.37,256.484 r270 top value=1.00Meg
R21 "ERJ-6ENF1004V" 0805_HV 40.411,260.6 r270 top value=1.00Meg
R22 "RC0603FR-071KL" 0603 195.868,152.752 r180 top value=1.00k
R23 "RC0603FR-071KL" 0603 196.592,155.184 r180 top value=1.00k
R24 "RC0603FR-071KL" 0603 204.772,137.24 r270 top value=1.00k
R25 "RC0603JR-070RL" 0603 245.094,242.668 r180 top value=0
R26 "RC1206FR-0747RL" 1206 227.999,245.871 r90 top value=47.0
R27 "ERJ-6ENF1004V" 0805_HV 190,246.481 r270 top value=1.00Meg
R28 "RC0603FR-0749K9L" 0603 244.284,245.221 r270 top value=49.9k
R29 "ERJ-6ENF1004V" 0805_HV 190,253.704 r270 top value=1.00Meg
R30 "ERJ-6ENF1004V" 0805_HV 201.113,240.141 r270 top value=1.00Meg
R31 "ERJ-6ENF1004V" 0805_HV 203.357,240.141 r270 top value=1.00Meg
R32 "ERJ-6ENF1004V" 0805_HV 189.983,259.869 r270 top value=1.00Meg
R33 "ERJ-6ENF1004V" 0805_HV 193.1,263.466 r180 top value=1.00Meg
R34 "RC1206FR-0747RL" 1206 206.537,246.807 r0 top value=47.0
R35 "ERJ-6ENF1004V" 0805_HV 201,265.839 r180 top value=1.00Meg
R36 "ERJ-6ENF1004V" 0805_HV 197,265.839 r180 top value=1.00Meg
R37 "RC0603FR-0710KL" 0603 221.364,264.637 r270 top value=10.0k
R40 "RC0603FR-0710RL" 0603 213.75,260.243 r270 top value=10.0
R41 "ERJ-6ENF1004V" 0805_HV 197.067,263.47 r0 top value=1.00Meg
R42 "ERJ-6ENF1004V" 0805_HV 201,263.484 r0 top value=1.00Meg
R43 "RC0603FR-0710KL" 0603 211.25,259.25 r0 top value=10.0k
R44 "RC0603FR-072K4L" 0603 221.401,267.98 r270 top value=2.40k
R45 "RC0603FR-0749K9L" 0603 223.855,263.77 r180 top value=49.9k
R46 "RC0603FR-07100KL" 0603 223.05,268.007 r90 top value=100k
R47 "RC0603FR-071KL" 0603 206.885,259.545 r180 top value=1.00k
R48 "CRCW12063R00JNEA" 1206 204.056,253.204 r0 top value=3.0
R49 "RC0603FR-0710KL" 0603 227.194,265.328 r180 top value=10.0k
R50 "RC0603FR-0749K9L" 0603 206.744,265.692 r0 top value=49.9k
R51 "RC0603JR-070RL" 0603 227.715,171.129 r180 top value=0
R52 "RC0603FR-071ML" 0603 222.197,179.526 r0 top value=1.00Meg
R53 "RC0603JR-070RL" 0603 222.253,164.461 r0 top value=0
R54 "RC0603FR-07100KL" 0603 218.341,173.226 r270 top value=100k
R55 "RC0603FR-07100KL" 0603 221.037,177.75 r0 top value=100k
R56 "RC0603FR-0712K4L" 0603 218.989,175.822 r0 top value=12.4k
R58 "RC0603JR-070RL" 0603 221.209,189.847 r90 top value=0
R59 "RC0603FR-071KL" 0603 215.691,204.158 r270 top value=1.00k
R60 "RC0603FR-071KL" 0603 227.947,201.032 r0 top value=1.00k
R61 "RC0603JR-070RL" 0603 231.65,188.097 r180 top value=0
R62 "RC0603FR-0749K9L" 0603 229.2,193.221 r0 top value=49.9k
R63 "RC1206FR-0747RL" 1206 242.281,227.306 r90 top value=47.0
R64 "RC0603JR-070RL" 0603 240.5,189.941 r0 top value=0
R65 "RC0603FR-071KL" 0603 238.246,201.434 r0 top value=1.00k
R66 "RC0603FR-0749K9L" 0603 239.024,192.85 r90 top value=49.9k
R67 "RC0603JR-070RL" 0603 196.714,207.807 r0 top value=0
R68 "ERJ-6ENF1004V" 0805_HV 236.601,232.933 r270 top value=1.00Meg
R69 "RC0603FR-071KL" 0603 214.09,224.5 r180 top value=1.00k
R70 "RC0603FR-0749K9L" 0603 200.352,209.481 r180 top value=49.9k
R71 "RC0603FR-071KL" 0603 232.663,227.656 r180 top value=1.00k
R72 "RC0603FR-07150KL" 0603 235.115,229.233 r270 top value=150k
R73 "RC0603FR-07150KL" 0603 227.69,230.583 r90 top value=150k
R75 "RC0603JR-070RL" 0603 215.411,30.926 r0 top value=0
R76 "RC0603FR-07150KL" 0603 231.94,235.988 r0 top value=150k
R77 "RC0603FR-0712K4L" 0603 227.69,233.714 r270 top value=12.4k
R78 "RC0603FR-071KL" 0603 243.054,219.5 r0 top value=1.00k
R79 "RC0603FR-0712K4L" 0603 239.382,14.334 r0 top value=12.4k
R80 "ERJ-6ENF1004V" 0805_HV 204.622,13.322 r0 top value=1.00Meg
R81 "ERJ-6ENF1004V" 0805_HV 208.535,13.322 r0 top value=1.00Meg
R82 "ERJ-6ENF1004V" 0805_HV 212.895,15.458 r0 top value=1.00Meg
R83 "RC0603FR-0724KL" 0603 215.763,14.846 r90 top value=24.0k
R84 "RC0603FR-0710KL" 0603 233.38,14.442 r0 top value=10.0k
R85 "RC0603FR-07100RL" 0603 213.088,137.196 r270 top value=100
R86 "RC0603FR-0724KL" 0603 216.563,12.096 r180 top value=24.0k
R87 "RC0603FR-0710KL" 0603 233.38,16.065 r0 top value=10.0k
R88 "RC0603FR-0712K4L" 0603 235.831,16.813 r270 top value=12.4k
R89 "RC0603FR-075K1L" 0603 245.704,24.122 r270 top value=5.10k
R90 "RC0603FR-0712K4L" 0603 235.939,23.938 r90 top value=12.4k
R91 "ERJ-6ENF1004V" 0805_HV 210.818,31.86 r270 top value=1.00Meg
R92 "ERJ-6ENF1004V" 0805_HV 210.818,27.889 r270 top value=1.00Meg
R93 "ERJ-6ENF1004V" 0805_HV 212.697,24.662 r0 top value=1.00Meg
R94 "RC0603FR-0710KL" 0603 242.492,21.225 r180 top value=10.0k
R95 "RC0603FR-0710RL" 0603 245.5,27.345 r90 top value=10.0
R96 "RC0603FR-0724KL" 0603 215.699,24.062 r270 top value=24.0k
R97 "RC0603FR-0710KL" 0603 233.377,22.942 r0 top value=10.0k
R98 "RC0603FR-07100RL" 0603 217.391,137.24 r270 top value=100
R99 "RC0603FR-0724KL" 0603 216.65,21.5 r180 top value=24.0k
R100 "RC0603FR-0710KL" 0603 233.377,24.662 r0 top value=10.0k
R101 "RC0603FR-0712K4L" 0603 236.557,26.566 r180 top value=12.4k
R102 "RC0603FR-0710KL" 0603 242.492,19.613 r0 top value=10.0k
R103 "RC0603FR-0712K4L" 0603 238.835,2.213 r0 top value=12.4k
R104 "ERJ-6ENF1004V" 0805_HV 204.907,6.271 r0 top value=1.00Meg
R105 "ERJ-6ENF1004V" 0805_HV 208.728,6.298 r0 top value=1.00Meg
R106 "ERJ-6ENF1004V" 0805_HV 212.651,6.271 r0 top value=1.00Meg
R107 "RC0603FR-0724KL" 0603 215.462,5.471 r270 top value=24.0k
R108 "RC0603FR-0710KL" 0603 233.643,4.082 r0 top value=10.0k
R109 "RC0603FR-07100RL" 0603 219.069,137.24 r270 top value=100
R110 "RC0603FR-0724KL" 0603 216.452,2.921 r180 top value=24.0k
R111 "RC0603FR-0710KL" 0603 233.615,5.857 r0 top value=10.0k
R112 "RC0603FR-0712K4L" 0603 236.182,6.271 r270 top value=12.4k
R113 "RC0603FR-0718KL" 0603 192.082,141.218 r180 top value=18.0k
R114 "ERJ-6ENF1004V" 0805_HV 142.891,202.837 r0 top value=1.00Meg
R115 "ERJ-6ENF1004V" 0805_HV 146.788,203.607 r0 top value=1.00Meg
R116 "ERJ-6ENF1004V" 0805_HV 147.825,200.553 r270 top value=1.00Meg
R117 "RC0603FR-0724KL" 0603 147.5,197.506 r180 top value=24.0k
R118 "RC0603FR-0710KL" 0603 147.439,179.343 r270 top value=10.0k
R119 "RC0603FR-07100RL" 0603 195.879,148.995 r0 top value=100
R120 "RC0603FR-0724KL" 0603 144.948,196.676 r90 top value=24.0k
R121 "RC0603FR-0710KL" 0603 149.058,179.343 r270 top value=10.0k
R122 "RC0603FR-07100KL" 0603 191.444,136.494 r270 top value=100k
R123 "RC0603FR-0722KL" 0603 192.998,136.494 r270 top value=22.0k
R124 "RC0603FR-0718KL" 0603 202.719,137.656 r270 top value=18.0k
R125 "ERJ-6ENF1004V" 0805_HV 74.915,208.047 r270 top value=1.00Meg
R126 "ERJ-6ENF1004V" 0805_HV 74.915,204.256 r270 top value=1.00Meg
R127 "ERJ-6ENF1004V" 0805_HV 74.915,200.393 r270 top value=1.00Meg
R128 "RC0603FR-0724KL" 0603 73.874,197.057 r0 top value=24.0k
R129 "RC0603FR-0710KL" 0603 75.565,178.75 r270 top value=10.0k
R130 "RC0603FR-07100RL" 0603 195.831,147.428 r0 top value=100
R131 "RC0603FR-0724KL" 0603 71.315,196.367 r270 top value=24.0k
R132 "RC0603FR-0710KL" 0603 73.93,178.8 r270 top value=10.0k
R133 "RC0603FR-07100KL" 0603 199.979,134.289 r270 top value=100k
R134 "RC0603FR-0722KL" 0603 198.391,134.257 r270 top value=22.0k
R135 "RC0603FR-07100RL" 0603 131.213,200.813 r270 top value=100
R136 "CRCW12063R00JNEA" 1206 118.504,202.947 r180 top value=3.0
R137 "RC0603FR-07100RL" 0603 131.25,203.971 r90 top value=100
R138 "RC0603FR-07100RL" 0603 58.779,200.643 r0 top value=100
R139 "CRCW12063R00JNEA" 1206 45.375,202.128 r180 top value=3.0
R140 "RC0603FR-07100RL" 0603 205.175,200.837 r270 top value=100
R141 "CRCW12063R00JNEA" 1206 191.504,203.397 r180 top value=3.0
R142 "RC0603FR-07100RL" 0603 58.729,202.293 r0 top value=100
R143 "RC0603FR-07100RL" 0603 205.568,203.465 r0 top value=100
R144 "RC0603FR-071KL" 0603 219.541,153.752 r0 top value=1.00k
R145 "RC0603FR-071KL" 0603 219.605,155.402 r0 top value=1.00k
R146 "RC0603FR-07100RL" 0603 207.557,166.463 r0 top value=100
R147 "RC0603FR-071KL" 0603 207.663,176.514 r90 top value=1.00k
R148 "RC0603FR-07100RL" 0603 209.691,176.514 r90 top value=100
R149 "RC0603FR-071KL" 0603 210.779,166.479 r180 top value=1.00k
R150 "RC0603FR-071KL" 0603 210.779,137.24 r270 top value=1.00k
R151 "RC0603FR-0710KL" 0603 211.348,161.278 r90 top value=10.0k
R152 "RC0603FR-072K4L" 0603 231.601,148.486 r90 top value=2.40k
R153 "RC0603FR-072K4L" 0603 231.826,144.245 r270 top value=2.40k
R154 "RC0603FR-0710KL" 0603 196.679,156.812 r0 top value=10.0k
R155 "RC0603FR-0710KL" 0603 212.965,161.278 r270 top value=10.0k
R156 "RC0603FR-071KL" 0603 222.872,146.628 r180 top value=1.00k
R157 "RC0603FR-071KL" 0603 228.439,152.297 r0 top value=1.00k
R158 "RC0603FR-071KL" 0603 219.688,144.885 r0 top value=1.00k
R159 "RC0603FR-0710KL" 0603 120.341,199.019 r0 top value=10.0k
R160 "RC0603FR-0710KL" 0603 47.352,197.71 r0 top value=10.0k
R161 "RC0603FR-0710KL" 0603 193.353,198.914 r0 top value=10.0k
RT1 "PPL16500NA2B7Y" FP-PPL16500NA2B7Y_RADIAL-MFG 190.5,56.5 r0 top value=50Ω
RT2 "TMP6131DECR" DEC0002A 208.463,131.895 r90 top
RV1 "MOV-14D561KTR" Bourns_MOV-14D561K 15.617,63.75 r90 top
RV2 "MOV-14D561KTR" Bourns_MOV-14D561K 15.65,18.5 r90 top
RV3 "MOV-14D561KTR" Bourns_MOV-14D561K 15.825,40.937 r90 top
T1 "750345636" FP-750345636_PTH10-MFG 217.598,239.28 r0 top
T2 "750345637" FP-750345637_PTH14-MFG 228.266,216.12 r270 top
TP1 "5015" Testpoint_Keystone_Miniature 126.952,171.212 r270 top
TP2 "5015" Testpoint_Keystone_Miniature 171.5,260.218 r0 top
TP3 "5015" Testpoint_Keystone_Miniature 193.421,166.787 r90 top
TP4 "5015" Testpoint_Keystone_Miniature 120.9,256.7 r0 top
TP5 "5015" Testpoint_Keystone_Miniature 54.25,174.365 r180 top
TP6 "5015" Testpoint_Keystone_Miniature 71.5,264.912 r0 top
TP7 "5015" Testpoint_Keystone_Miniature 232.688,162.862 r270 top
TP8 "5015" Testpoint_Keystone_Miniature 219.884,161.902 r0 top
TP9 "5015" Testpoint_Keystone_Miniature 223.3,189.36 r90 top
TP10 "5015" Testpoint_Keystone_Miniature 232.284,192.53 r270 top
TP11 "5015" Testpoint_Keystone_Miniature 242.806,192.755 r90 top
TP12 "5015" Testpoint_Keystone_Miniature 205.277,215.233 r270 top
TP13 "5015" Testpoint_Keystone_Miniature 210.396,19.243 r270 top
TP14 "5015" Testpoint_Keystone_Miniature 213.453,132.265 r270 top
TP15 "5015" Testpoint_Keystone_Miniature 217.391,132.265 r270 top
TP16 "5015" Testpoint_Keystone_Miniature 220.113,132.186 r90 top
TP17 "5015" Testpoint_Keystone_Miniature 195.391,142.103 r270 top
TP18 "5015" Testpoint_Keystone_Miniature 201.704,140.729 r180 top
TP19 "5015" Testpoint_Keystone_Miniature 132,196.03 r90 top
TP20 "5015" Testpoint_Keystone_Miniature 59.642,196.937 r90 top
TP21 "5015" Testpoint_Keystone_Miniature 203.593,192.53 r90 top
TP22 "5015" Testpoint_Keystone_Miniature 230.909,156.094 r180 top
TP23 "5015" Testpoint_Keystone_Miniature 226.45,157.562 r0 top
TP24 "5015" Testpoint_Keystone_Miniature 226.917,131.752 r180 top
TP25 "5015" Testpoint_Keystone_Miniature 229.768,138.514 r180 top
TP26 "5015" Testpoint_Keystone_Miniature 224.339,151.877 r0 top
TP27 "5015" Testpoint_Keystone_Miniature 224.212,144.421 r0 top
U1 "TMCS1123B2AQDVGR" DVG0010A-MFG 119.145,174.875 r0 top
U2 "TMCS1123B2AQDVGR" DVG0010A-MFG 187.024,174.957 r0 top
U3 "TMCS1123B2AQDVGR" DVG0010A-MFG 46,175 r0 top
U4 "ISOTMP35BEDFQRQ1" DFQ0007A-MFG 87.225,177.441 r0 top
U5 "ISOTMP35BEDFQRQ1" DFQ0007A-MFG 160.1,177.53 r0 top
U6 "ISOTMP35BEDFQRQ1" DFQ0007A-MFG 14.484,178.093 r0 top
U7 "UCC287501DBVR" DBV0006A-MFG 210.386,262.7 r270 top
U8 "PC817X4NSZ0F" DIP762W60P254L460H350Q4B 215.25,267.436 r180 top
U9 "TL431BQDBZT" DBZ0003A_N 227.534,267.98 r0 top
U10 "TPS54202DDCR" DDC0006A_N 223.401,175.284 r180 top
U11 "TLV76133DCYR" DCY0004A-MFG 227.909,165.421 r90 top
U12 "TLV76133DCYR" DCY0004A-MFG 221,195.5 r270 top
U13 "LM25180NGUR" NGU0008C 231.14,230.983 r180 top
U14 "TLV76133DCYR" DCY0004A-MFG 220.579,34.828 r90 top
U15 "AMC1350DWVQ1" DWV0008A-MFG 225.127,15.346 r0 top
U16 "TLV9062IDGKR" DGK0008A_N 238.737,8.067 r270 top
U17 "AMC1350DWVQ1" DWV0008A-MFG 225.127,24.097 r0 top
U18 "TLV9062IDGKR" DGK0008A_N 241.582,23.797 r0 top
U19 "AMC1350DWVQ1" DWV0008A-MFG 225.127,5.47 r0 top
U20 "AMC1350DWVQ1" DWV0008A-MFG 148.423,188 r270 top
U21 "TLV9062IDGKR" DGK0008A_N 196.94,138.044 r0 top
U22 "AMC1350DWVQ1" DWV0008A-MFG 74.565,187.5 r270 top
U23 "UCC5350MCDR" D0008B_HV 125.251,202.312 r180 top
U24 "UCC5350MCDR" D0008B_HV 52,201.493 r180 top
U25 "UCC5350MCDR" D0008B_HV 198.172,202.762 r180 top
U26 "ISO6721BQDRQ1" D0008A-MFG 209.032,170.937 r90 top
U27 "F2800137PT" PT0048A-MFG 209.838,152.127 r0 top

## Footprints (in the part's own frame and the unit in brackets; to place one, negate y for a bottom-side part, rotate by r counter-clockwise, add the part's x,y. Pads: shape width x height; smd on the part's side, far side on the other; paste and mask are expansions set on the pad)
157PUM-SI_3500x5000 [mm] "TH, 2-Leads, Dia 35mm, Pin Spacing 10mm"
  rect 2.5x2.5 hole 2: 1(-5,0)
  round 2.5 hole 2: 2(5,0)
  silkscreen extent -18,-18 18,18, body extent -18,-18 18.01,18, height 52.01
0603 [mm] "0603 from SM-752 data"
  rect 1x0.95 smd: 1(-0.8,0) 2(0.8,0)
  silkscreen extent -1.52,-0.69 1.52,0.69, body extent -0.87,-0.47 0.87,0.47, height 1
0805_HV [mil] "0805 with 30mil clearance between pads"
  rect 50x63 smd: 1(-40,0) 2(40,0)
  silkscreen extent -74,-40 74,40, body extent -43,-29 43,29, height 57
1206 [mm] "1206 from SM-752 data"
  rect 1.3x1.85 smd: 1(-1.45,0) 2(1.45,0)
  silkscreen extent -2.4,-1.21 2.4,1.21, body extent -1.7,-0.9 1.7,0.9, height 1.35
1206_180 [mm] "1206_180"
  rect 1.1x1.6 smd: 1(-1.7,0) 2(1.7,0)
  silkscreen extent -0.9,-1 0.9,1, body extent -1.75,-0.95 1.75,0.95, height 1.8
Bourns_MOV-14D561K [mm] "TH, 2-Leads, Dia 16.5mm"
  round 1.65 hole 1.15: 1(-3.75,-0.5) 2(3.75,0.5)
  silkscreen extent -8.25,-3 8.25,3, body extent -8.25,-3 8.25,3, height 22
CAPRD1000W60D900H1200 [mm] "Disk, Radial Capacitor"
  round 1.35 hole 0.85: 1(-5,0) 2(5,0)
  silkscreen extent -5.3,-3.5 5.3,3.5, body extent -4.48,-3.5 4.48,3.5, height 11.99
CE_Mark_5mm [mm] "Minimum text height for CE Mark"
  silkscreen extent -3.5,-2.5 3.5,2.5
Chemi-Con_500x1100 [mm] "TH, 2-Leads, Dia 5mm, Lead Sapcing 2mm"
  rect 1.25x1.25 hole 0.75: 1(-1,0)
  round 1.25 hole 0.75: 2(1,0)
  silkscreen extent -2.8,-2.8 2.8,2.8, body extent -2.75,-2.75 2.75,2.75, height 12.5
D0008A-MFG [mm]
  rrect17% 1.55x0.6 smd paste+0 mask+0: 1(-2.7,1.905) 2(-2.7,0.635) 3(-2.7,-0.635) 4(-2.7,-1.905) 5(2.7,-1.905) 6(2.7,-0.635) 7(2.7,0.635) 8(2.7,1.905)
  silkscreen extent -4.17,-2.5 1.5,2.5, body extent -3.57,-2.75 3.57,2.75, height 0.25
D0008B_HV [mm] "SOIC, 8-Leads, Body 4.9x3.9mm, Pitch 1.27mm, HV / Isolation option"
  rrect17% 1.4x0.6 smd: 1(-2.75,1.905) 2(-2.75,0.635) 3(-2.75,-0.635) 4(-2.75,-1.905) 5(2.75,-1.905) 6(2.75,-0.635) 7(2.75,0.635) 8(2.75,1.905)
  silkscreen extent -3.3,-2.5 0.9,2.5, body extent -3,-2.45 3,2.45, height 1.63
DBV0006A-MFG [mm]
  rrect17% 1.1x0.6 smd paste+0 mask+0: 1(-1.3,0.95) 2(-1.3,0) 3(-1.3,-0.95) 4(1.3,-0.95) 5(1.3,0) 6(1.3,0.95)
  silkscreen extent -2.52,-1.53 0.35,1.53, body extent -1.95,-1.78 1.95,1.78, height 0.25
DBZ0003A_N [mm] "SOT23, 3-Leads, Body 2.9x1.3mm, Pitch 0.95mm, Lead Span 2.4mm, IPC Medium Density"
  rrect17% 1x0.6 smd: 1(-1.2,0.95) 2(-1.2,-0.95) 3(1.2,0)
  silkscreen extent 0.2,-1.5 0.7,1.5, body extent -1.26,-1.46 1.26,1.46, height 0.98
DCY0004A-MFG [mm]
  rrect11% 2.15x0.95 smd paste+0 mask+0: 1(-2.9,2.3) 2(-2.9,0) 3(-2.9,-2.3)
  rrect5% 2.15x3.25 smd paste+0 mask+0: 4(2.9,0)
  silkscreen extent -4.7,-3.35 1.85,3.35, body extent -4.08,-3.45 4.08,3.45, height 0.25
DDC0006A_N [mm]
  rrect17% 1x0.6 smd: 1(-1.375,0.95) 2(-1.375,0) 3(-1.375,-0.95) 4(1.375,-0.95) 5(1.375,0) 6(1.375,0.95)
  silkscreen extent -1.75,-1.52 0.7,1.53, body extent -1.43,-1.48 1.43,1.49, height 0.92
DEC0002A [mm] "X1SON-2"
  rrect57% 0.35x0.6 smd paste-0.5 mask-0.05: 1(-0.325,0) 2(0.325,0)
  rrect33% 0.3x0.5 on Top Paste: 1S(-0.35,0) 2S(0.35,0)
  body extent -0.5,-0.3 0.5,0.3, height 0.5
DFQ0007A-MFG [mm]
  rrect17% 1.55x0.6 smd paste+0 mask+0: 1(-2.7,1.905) 2(-2.7,0.635) 3(-2.7,-0.635) 4(-2.7,-1.905) 5(2.7,-1.905) 7(2.7,1.905)
  rrect6% 1.55x2.36 smd paste+0 mask+0: 6(2.7,0)
  silkscreen extent -4.14,-2.5 1.55,2.5, body extent -3.57,-2.75 3.57,2.75, height 0.25
DGK0008A_N [mm] "TSOP, 8-Leads, Body 3x3mm, Pitch 0.65mm, IPC Medium Density"
  oval 1.35x0.45 smd: 1(-2.225,0.975) 2(-2.225,0.325) 3(-2.225,-0.325) 4(-2.225,-0.975) 5(2.225,-0.975) 6(2.225,-0.325) 7(2.225,0.325) 8(2.225,0.975)
  silkscreen extent -2.75,-1.55 0.95,1.55, body extent -2.45,-1.5 2.45,1.5, height 0.96
DIP762W60P254L460H350Q4B [mm] "LITE-ON"
  rrect8% 1.2x1.2 hole 0.85: 1(-3.81,1.27)
  round 1.2 hole 0.85: 2(-3.81,-1.27) 3(3.81,-1.27) 4(3.81,1.27)
  silkscreen extent -4.29,-2.29 3.25,2.3, body extent -3.94,-2.29 3.94,2.3, height 4.3
DVG0010A-MFG [mm]
  rrect6% 1.65x4.41 smd paste+0 mask+0: 1(-4.875,2.54) 2(-4.875,-2.54)
  rrect17% 1.65x0.6 smd paste+0 mask+0: 3(4.875,-4.445) 4(4.875,-3.175) 5(4.875,-1.905) 6(4.875,-0.635) 7(4.875,0.635) 8(4.875,1.905) 9(4.875,3.175) 10(4.875,4.445)
  silkscreen extent -6.37,-5.25 3.67,5.25, body extent -5.8,-5.5 5.8,5.5, height 0.25
DWV0008A-MFG [mm]
  rrect17% 1.8x0.6 smd paste+0 mask+0: 1(-5.45,1.905) 2(-5.45,0.635) 3(-5.45,-0.635) 4(-5.45,-1.905) 5(5.45,-1.905) 6(5.45,-0.635) 7(5.45,0.635) 8(5.45,1.905)
  silkscreen extent -7.1,-2.98 3.8,2.98, body extent -6.45,-3.22 6.45,3.22, height 0.25
FCC_disclaimer [mm]
Fiducial10-20 [mm]
  round 1 smd mask+0.5: 1(0,0)
  Top Layer keep-out circle w1.178: c0,0 r0.5
FP-0525025.MXEP_AXIAL-MFG [mm]
  rrect5% 2.15x2.15 hole 1.4 paste-1000 mask+0: 1(-22.42,0)
  round 2.15 hole 1.4 paste-1000 mask+0: 2(22.42,0)
  silkscreen extent -16.92,-3.64 16.92,3.64, body extent -23.59,-3.74 23.59,3.74, height 0.25
FP-750345636_PTH10-MFG [mm]
  rrect5% 1.87x1.87 hole 1.22 paste-1000 mask+0: 1(-6.5,7.8)
  round 1.87 hole 1.22 paste-1000 mask+0: 2(-6.5,3.9) 3(-6.5,0) 4(-6.5,-3.9) 5(-6.5,-7.8) 6(6.5,-7.8) 7(6.5,-3.9) 8(6.5,0) 9(6.5,3.9) 10(6.5,7.8)
  silkscreen extent -9.47,-10.5 8.75,10.5, body extent -8.85,-10.6 8.85,10.6, height 0.25
FP-750345637_PTH14-MFG [mm]
  rrect6% 1.7x1.7 hole 1.1 paste-1000 mask+0: 1(-7.62,7.62)
  round 1.7 hole 1.1 paste-1000 mask+0: 2(-7.62,5.08) 3(-7.62,2.54) 4(-7.62,0) 5(-7.62,-2.54) 6(-7.62,-5.08) 7(-7.62,-7.62) 8(7.62,-7.62) 9(7.62,-5.08) 11(7.62,0) 12(7.62,2.54) 13(7.62,5.08) 14(7.62,7.62)
  silkscreen extent -11.22,-9.5 10.5,9.5, body extent -10.6,-9.6 10.6,9.6, height 0.25
FP-970130365_SPCAER_M3-MFG [mm]
  round 3.15 hole 3.15 unplated paste-1000 mask+0: ""(0,0)
  body extent -3.46,-3 3.46,3, height 13.1
FP-890334027012CS_RADIAL-MFG [mm]
  rrect6% 1.7x1.7 hole 1.1 paste-1000 mask+0: 1(-13.75,0)
  round 1.7 hole 1.1 paste-1000 mask+0: 2(13.75,0)
  silkscreen extent -15.75,-6.75 15.75,6.75, body extent -15.85,-6.85 15.85,6.85, height 0.25
FP-GCM188R71H104KA57J_0603-MFG [mm]
  rrect15% 0.65x0.7 smd paste+0 mask+0: 1(-0.675,0) 2(0.675,0)
  silkscreen extent -0.85,-0.75 0.85,0.75, body extent -1.1,-0.55 1.1,0.55, height 0.25
FP-IKW50N65F5FKSA1_HOR_V1 [mm]
  rrect4% 2.5x2.5 hole 1.65 paste-2539.97 mask+0: 1(-5.45,15.047)
  round 2.5 hole 1.65 paste-2539.97 mask+0: 2(0,19.047) 3(5.45,15.047)
  round 3.65 hole 8 unplated paste-2539.97 mask+0: ""(0,-4.305)
  silkscreen extent -8.06,-10.55 8.07,10.55, body extent -7.96,-10.48 7.96,19.28, height 5.02
FP-IKW50N65F5FKSA1_HOR_V2 [mm]
  rrect4% 2.5x2.5 hole 1.65 paste-2539.97 mask+0: 1(-5.45,19.047)
  round 2.5 hole 1.65 paste-2539.97 mask+0: 2(0,15.047) 3(5.45,19.047)
  round 3.65 hole 8 unplated paste-2539.97 mask+0: ""(0,-4.305)
  silkscreen extent -8.06,-10.55 8.07,10.55, body extent -7.96,-10.48 7.96,19.28, height 5.02
FP-PPL16500NA2B7Y_RADIAL-MFG [mm]
  rrect5% 1.85x1.85 hole 1.2 paste-1000 mask+0: 1(-5,0)
  round 1.85 hole 1.2 paste-1000 mask+0: 2(5,0)
  silkscreen extent -9,-3.75 9,3.75, body extent -9.1,-3.85 9.1,3.85, height 0.25
FP-RHRG30120-MFG_HOR [mm]
  rrect4% 2.6x2.6 hole 1.7 paste-2539.97 mask+0: 1(5.45,-17.405)
  round 2.6 hole 1.7 paste-2539.97 mask+0: 2(-5.45,-17.405)
  round 8 hole 8 unplated paste-2539.97 mask+0: ""(0,4.825)
  silkscreen extent -7.94,-17.53 7.94,10.41, body extent -7.81,-17.71 7.81,10.29, height 4.82
FP-SA2-3000-CLT-STD_AXIAL-MFG [mm]
  rrect6% 1.75x1.75 hole 1.15 paste-1000 mask+0: 1(-7.95,0)
  round 1.75 hole 1.15 paste-1000 mask+0: 2(7.95,0)
  silkscreen extent -4.65,-4.3 4.65,4.3, body extent -8.93,-4.4 8.93,4.4, height 0.25
FP-YXS51020T_PTH_IND_58MM0_70MM0-MFG [mm]
  rrect1% 6.8x6.8 hole 4.5 paste-1000 mask+0: 1(-32,0)
  round 6.8 hole 4.5 paste-1000 mask+0: 2(32,0)
  silkscreen extent -36.22,-29 35,29, body extent -35.5,-29.1 35.5,29.1, height 0.25
FP-YXS80874T_PTH_CMC_66MM0_56MM0-MFG [mm]
  rrect2% 4.45x4.45 hole 2.95 paste-1000 mask+0: 1(-24,18)
  round 4.45 hole 2.95 paste-1000 mask+0: 2(24,18) 3(-24,0) 4(24,0) 5(-24,-18) 6(24,-18)
  silkscreen extent -28.72,-33 28,33, body extent -28.1,-33.1 28.1,33.1, height 0.25
IEC_HighVoltage_Small [mm]
  silkscreen extent -2.72,-2.24 2.72,2.47
IEC_HotSurface_Small [mm]
  silkscreen extent -2.72,-2.36 2.72,2.35
LTST-C193_Red [mm] "SMD, 2-Leads, Body1.6x0.8mm"
  rect 0.8x0.8 smd: 1(-0.75,0) 2(0.75,0)
  silkscreen extent -1.2,-0.9 1.85,0.9, body extent -0.85,-0.45 0.85,0.45, height 0.45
